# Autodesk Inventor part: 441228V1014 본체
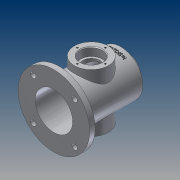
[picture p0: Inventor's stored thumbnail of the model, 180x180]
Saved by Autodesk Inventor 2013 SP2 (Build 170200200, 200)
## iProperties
Created: 2014-12
Part Number: 441228V1014 본체
Material: 알루미늄 6061
Document SubType Name: Modeling
Designer: CADB105
Density: 2.71 g/cm^3
Mass: 478.804 g
Surface Area: 623.216 cm^2
Volume: 176.681 cm^3
Author: CADB105
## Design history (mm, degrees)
sketch "스케치1"
  geometry: L1 (0, 86.22)-(0, -86.22); L2 (-52.5, -47)-(0, -47); L3 (52.5, -47)-(52.5, -55); L4 (0, -55)-(-52.5, -55); L5 (-52.5, -55)-(-52.5, -47); L6 (-32.5, 43)-(0, 43); L7 (0, -55)-(-32.5, -55); L8 (-32.5, -55)-(-32.5, 43); L9 (-32.5, -55)-(0, -55); L10 (0, 43)-(0, -55); L11 (0, -55)-(0, -47); 2 further points
  constraints: 22 end point, 3 collinear, 3 parallel, 2 horizontal, 2 point on line, 2 vertical alignment, 1 coincident, 1 midpoint, 1 perpendicular, 1 vertical
  dimensions: "d0" = 55 distance from line of point (0, 0) L4; "d1" = 8 distance between parallel lines of L2 L4; "d4" = 65 diameter of L8 L1; "d5" = 98 distance of L7.end L6.start; "d8" = 105 diameter of L5 L1
revolve "회전1" stored, may be unused: angle "d6" = 90 deg
feature "쉘1" dims "d7" = 5
revolve "회전2" stored, may be unused: angle "d9" = 90 deg
sketch "스케치2"
  geometry: C1 r 52.5 at (0, 0) reference
sketch "스케치3"
  geometry: C1 r 27.5 at (0, 0) reference
extrude "돌출1" cut sketch "스케치3" distance "d10" = 15; taper "d11" = 0 deg
sketch "스케치4"
  geometry: C1 r 32.5 at (0, 0) reference; C2 r 22.5 at (0, 0)
  constraints: 1 centre point, 1 coincident
  dimensions: "d12" = 45 diameter of C2
extrude "돌출2" join sketch "스케치4" distance "d13" = 8; taper "d14" = 0 deg
node "작업 평면1"
sketch "스케치5"
  geometry: C1 r 25 at (0, 0); 1 further point
  constraints: 1 centre point, 1 coincident
  dimensions: "d16" = 50 diameter of C1
extrude "돌출3" join sketch "스케치5" stored distance "d17" = 8; taper "d18" = 0 deg
hole "구멍1" diameter "d21" = 25; stored, may be unused: countersink angle "d25" = 90 deg, drill point angle "d27" = 0 deg; dims "d19" = 10, "d20" = 10, "d22" = 6, "d23" = 32, "d24" = 12, "d26" = 8
chamfer "모따기1" distance "d28" = 1; stored, may be unused: second distance "d29" = 2, angle "d30" = 45 deg
fillet "모깎기1" dims "d31" = 0.3
sketch "스케치6"
  geometry: C1 r 25 at (0, 0) reference; 1 further point
  constraints: 1 vertical alignment
  dimensions: "d32" = 20.5 distance of point (0, 20.5) C1.centre
hole "구멍2" sketch "스케치6" at (0, 20.5) diameter "d33" = 2.459; stored, may be unused: countersink angle "d37" = 90 deg, drill point angle "d39" = 118 deg; dims "d34" = 6, "d35" = 32, "d36" = 12, "d38" = 8
sketch "스케치7"
  geometry: C1 r 22.5 at (0, 0) reference; 1 further point
  constraints: 1 vertical alignment
  dimensions: "d43" = 17.5 distance of point (0, 17.5) C1.centre
hole "구멍3" sketch "스케치7" at (0, 17.5) diameter "d44" = 2.459; stored, may be unused: countersink angle "d48" = 90 deg, drill point angle "d50" = 118 deg; dims "d45" = 6, "d46" = 4, "d47" = 2, "d49" = 8
hole "구멍4" diameter "d56" = 27; stored, may be unused: countersink angle "d60" = 90 deg, drill point angle "d62" = 0 deg; dims "d54" = 10, "d55" = 10, "d57" = 6, "d58" = 4, "d59" = 2, "d61" = 8
sketch "스케치8" dims "d63" = 86
  geometry: L1 (-52.5, 0)-(52.5, 0); L2 (0, 0)-(-30.406, 30.406); C1 r 32.5 at (0, 0) reference; A1 r 52.5 centre (0, 0) between (-52.5, 0) and (52.5, 0) reference; 2 further points
  constraints: 4 end point, 3 coincident, 2 point on circle, 1 horizontal, 1 midpoint, 3 other
  dimensions: "d64" = 45 deg angle of L1 L2
hole "구멍5" sketch "스케치8" at (-30.406, 30.406) diameter "d66" = 8; stored, may be unused: countersink angle "d70" = 90 deg, drill point angle "d72" = 0 deg; dims "d67" = 6, "d68" = 4, "d69" = 2, "d71" = 8
node "작업 평면3"
sketch "스케치9"
  geometry: L1 (32.5, 43)-(-32.5, 43) reference; 2 further points
  constraints: 1 vertical alignment, 1 other
  dimensions: "d77" = 9 distance from line of L1 point (0, 34)
feature "엠보싱1" sketch "스케치9" dims "d78" = 1, "d79" = 0
node "솔리드1"
pattern_circular "원형 패턴1" dims angle "d41" = 360 deg
mirror "대칭1"
pattern_circular "원형 패턴2" dims angle "d52" = 360 deg
pattern_circular "원형 패턴3" dims angle "d74" = 360 deg
other parameters: "d15" = 42.5, "d76" = 32.5
